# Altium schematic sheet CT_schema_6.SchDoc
size 302 x 172 mm
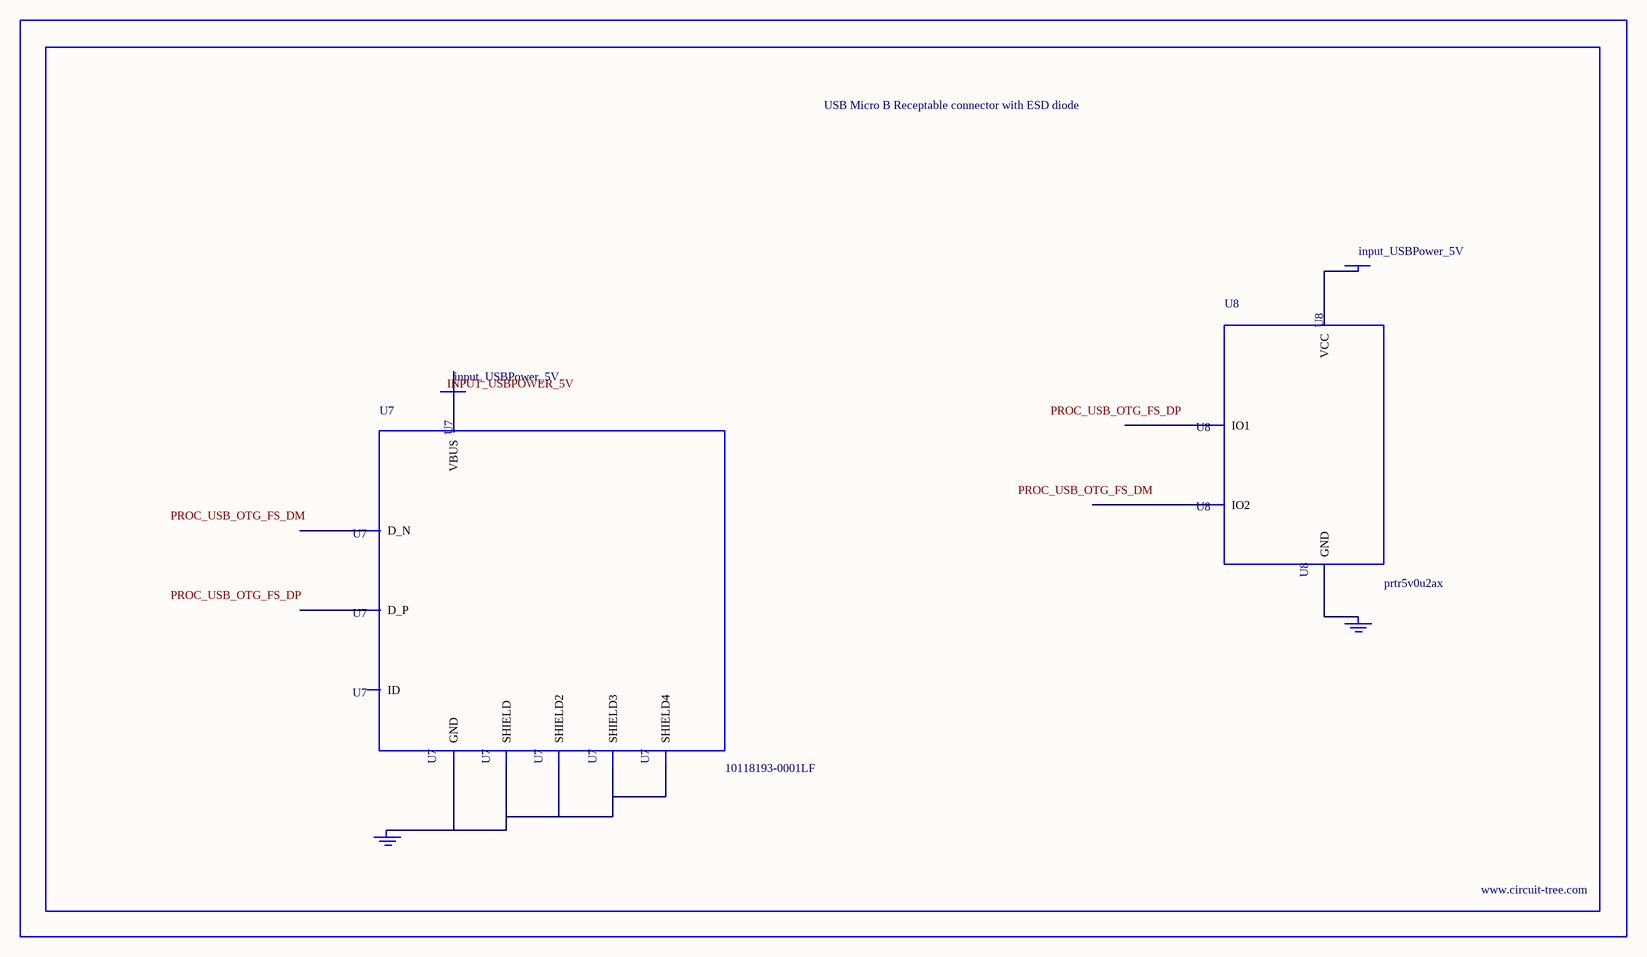
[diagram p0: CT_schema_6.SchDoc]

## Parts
BORDER5  (no value)
GND_INSTANCE_5_0  (no value)
GND_INSTANCE_5_1  (no value)
POWER_INSTANCE_5_0  input_USBPower_5V
POWER_INSTANCE_5_1  input_USBPower_5V
U7  10118193-0001LF  [FCI_10118193-0001LF]
U8  prtr5v0u2ax  [SOT143B]

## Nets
NetGND_INSTANCE_5_0_0: GND_INSTANCE_5_0.0(GND) U7.5(GND) U7.6(SHIELD) U7.7(SHIELD2) U7.8(SHIELD3) U7.9(SHIELD4)
NetGND_INSTANCE_5_1_0: GND_INSTANCE_5_1.0(GND) U8.1(GND)
NetPOWER_INSTANCE_5_0_0: POWER_INSTANCE_5_0.0(PWR) U7.1(VBUS)
NetPOWER_INSTANCE_5_1_0: POWER_INSTANCE_5_1.0(PWR) U8.4(VCC)

Not connected (* = marked no-connect by the designer): U7 2(D_N) 3(D_P) 4(ID); U8 2(IO1) 3(IO2)

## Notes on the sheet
- Labels drawn without touching a wire or pin: INPUT_USBPOWER_5V, PROC_USB_OTG_FS_DM, PROC_USB_OTG_FS_DP

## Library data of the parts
BORDER5 = BORDER_PAGE5
GND_INSTANCE_5_0 GND_INSTANCE_5_1 = GND
POWER_INSTANCE_5_0 POWER_INSTANCE_5_1 = PWR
